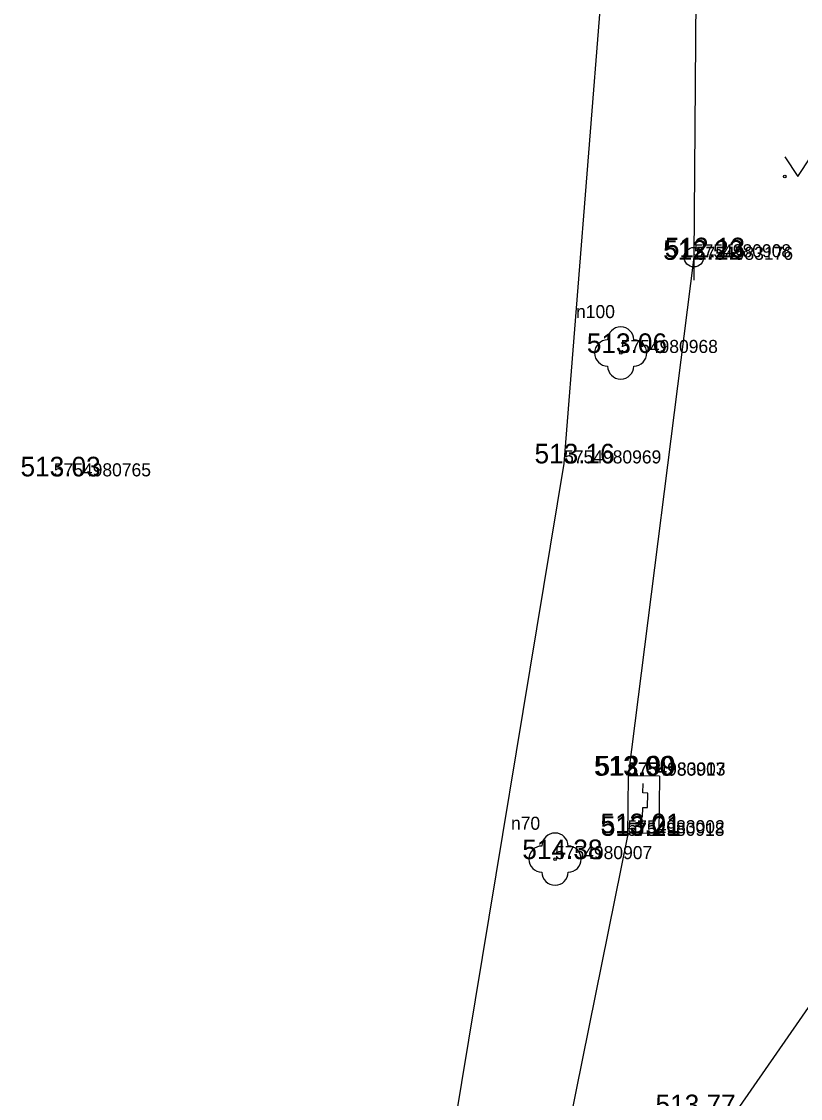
# Model space of a CAD drawing. Extents: x -669251 to -668549, y -1128351 to -1127698.
# Drawn here: x -669028.32 to -668998.51, y -1127892.22 to -1127851.01 of the extents above; entities that cross this region are included whole.
import ezdxf

# ---------------------------------------------------------------- set-up
doc = ezdxf.new("R2010")
doc.units = 0
for name, color, linetype in [('Vrstva 1', 7, 'Continuous'), ('Vrstva 14', 7, 'Continuous'), ('Vrstva 2', 7, 'Continuous'), ('Vrstva 22', 7, 'Continuous'), ('Vrstva 24', 7, 'Continuous'), ('Vrstva 27', 7, 'Continuous'), ('Vrstva 3', 7, 'Continuous'), ('Vrstva 36', 7, 'Continuous'), ('Vrstva 47', 7, 'Continuous'), ('Vrstva 5', 7, 'Continuous')]:
    doc.layers.add(name, color=color, linetype=linetype)

msp = doc.modelspace()

# ---------------------------------------------------------------- linework, layer by layer
at = {"layer": 'Vrstva 1'}
for p, q in [((-669002.591, -1127860.035), (-669002.591, -1127860.035)), ((-669002.516, -1127860.131), (-669002.516, -1127860.131)), ((-669005.391, -1127863.696), (-669005.391, -1127863.696)), ((-669007.556, -1127867.922), (-669007.556, -1127867.922)), ((-669027.083, -1127868.418), (-669027.083, -1127868.418)), ((-669005.106, -1127879.874), (-669005.106, -1127879.874)), ((-669005.098, -1127879.863), (-669005.098, -1127879.863)), ((-669005.137, -1127882.175), (-669005.137, -1127882.175)), ((-669005.131, -1127882.075), (-669005.131, -1127882.075)), ((-669007.904, -1127883.066), (-669007.904, -1127883.066))]:
    msp.add_line(p, q, dxfattribs=at)
at = {"layer": 'Vrstva 14'}
for p, q in [((-669007.556, -1127867.922), (-669005.286, -1127839.263)), ((-669002.505, -1127848.461), (-669002.591, -1127860.035)), ((-669002.591, -1127860.035), (-669005.106, -1127879.874)), ((-669012.846, -1127899.967), (-669007.556, -1127867.922)), ((-669005.137, -1127882.175), (-669009.543, -1127904.044))]:
    msp.add_line(p, q, dxfattribs=at)
at = {"layer": 'Vrstva 22'}
for centre in [(-669005.391, -1127863.696), (-669007.904, -1127883.066)]:
    msp.add_circle(centre, 0.05, dxfattribs=at)
for centre, start, end in [((-669005.391, -1127863.196), 0, 180), ((-669005.891, -1127863.696), 90, 270), ((-669004.891, -1127863.696), 270, 90), ((-669005.391, -1127864.196), 180, 0), ((-669007.904, -1127882.566), 0, 180), ((-669008.404, -1127883.066), 90, 270), ((-669007.404, -1127883.066), 270, 90), ((-669007.904, -1127883.566), 180, 0)]:
    msp.add_arc(centre, 0.5, start, end, dxfattribs=at)
at = {"layer": 'Vrstva 24'}
for p, q in [((-669005.106, -1127879.874), (-669005.137, -1127882.175)), ((-669003.906, -1127879.89), (-669005.106, -1127879.874)), ((-669003.906, -1127879.89), (-669003.936, -1127882.091)), ((-669003.936, -1127882.091), (-669005.136, -1127882.075))]:
    msp.add_line(p, q, dxfattribs=at)
msp.add_lwpolyline([(-669004.552, -1127881.456), (-669004.546, -1127881.088), (-669004.363, -1127881.09), (-669004.356, -1127880.539), (-669004.539, -1127880.535), (-669004.535, -1127880.167)], dxfattribs=at)
at = {"layer": 'Vrstva 27'}
msp.add_line((-669002.59, -1127859.655), (-669002.59, -1127860.905), dxfattribs=at)
msp.add_circle((-669002.59, -1127860.03), 0.375, dxfattribs=at)
at = {"layer": 'Vrstva 36'}
for p, q in [((-668999.116, -1127856.189), (-668998.616, -1127856.939)), ((-668998.616, -1127856.939), (-668998.116, -1127856.189))]:
    msp.add_line(p, q, dxfattribs=at)
msp.add_circle((-668999.115, -1127856.939), 0.05, dxfattribs=at)
at = {"layer": 'Vrstva 5'}
msp.add_line((-668996.268, -1127885.924), (-669002.798, -1127895.331), dxfattribs=at)

# ---------------------------------------------------------------- texts
at = {"layer": 'Vrstva 2'}
for s, p in [('5754980908', (-669002.591, -1127860.035)), ('5754983176', (-669002.516, -1127860.131)), ('5754980968', (-669005.391, -1127863.696)), ('5754980969', (-669007.556, -1127867.922)), ('5754980765', (-669027.083, -1127868.418)), ('5754980917', (-669005.106, -1127879.874)), ('5754983003', (-669005.098, -1127879.863)), ('5754980918', (-669005.137, -1127882.175)), ('5754983002', (-669005.131, -1127882.075)), ('5754980907', (-669007.904, -1127883.066))]:
    msp.add_text(s, height=0.5, dxfattribs=at).set_placement(p)
at = {"layer": 'Vrstva 3'}
for s, p in [('512.22 ', (-669003.768, -1127860.131)), ('512.13 ', (-669003.701, -1127860.035)), ('513.06 ', (-669006.687, -1127863.696)), ('513.16 ', (-669008.689, -1127867.922)), ('513.03 ', (-669028.357, -1127868.418)), ('513.00 ', (-669006.415, -1127879.874)), ('512.99 ', (-669006.355, -1127879.863)), ('513.01 ', (-669006.168, -1127882.075)), ('513.21 ', (-669006.152, -1127882.175)), ('514.38 ', (-669009.156, -1127883.066)), ('513.77 ', (-669004.059, -1127892.827))]:
    msp.add_text(s, height=0.75, dxfattribs=at).set_placement(p)
at = {"layer": 'Vrstva 47'}
for s, p in [('n100', (-669007.1, -1127862.362)), ('n70', (-669009.589, -1127881.942))]:
    msp.add_text(s, height=0.5, dxfattribs=at).set_placement(p)

doc.saveas('drawing.dxf')
